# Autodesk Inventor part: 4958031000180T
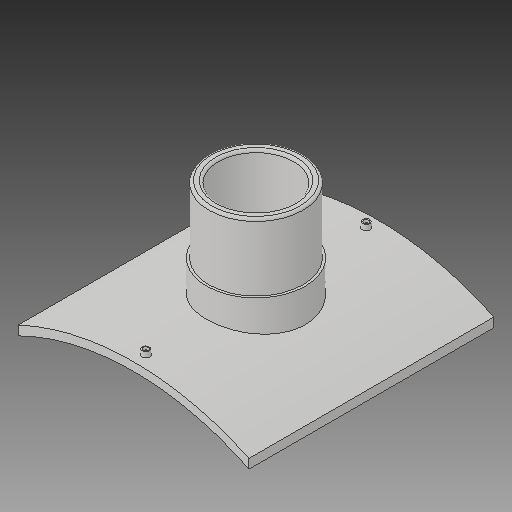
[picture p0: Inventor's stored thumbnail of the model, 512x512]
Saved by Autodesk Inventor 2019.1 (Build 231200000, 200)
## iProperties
Created: 2017-10
Part Number: 4958031000180T
Material: Generic
Description: PLASSON BRANCH SADDLE 1000x180
Document SubType Name: Modeling
Designer: KIM
Mass: 2754.05 g
Surface Area: 3037.44 cm^2
Volume: 2754.05 cm^3
Density: 1 g/cm^3
Appearance: Default
Author: KIM
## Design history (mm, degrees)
derived "495803.ipt"
feature "Solid1::495803.ipt"
tag "TaggingFeature1"
body "Solid1"
other parameters: "d1" = 16, "d2" = 443, "d4" = 0, "d12" = 525.6, "d13" = 14, "d14" = 211.5, "d16" = 5 deg, "d18" = 4, "d19" = 14, "d20" = 0, "d21" = 3, "d22" = 0, "d24" = 189, "d25" = 16, "d26" = 144, "d28" = 0, "d29" = 9.6, "d31" = 0, "d32" = 92, "d33" = 0, "d37" = 128.8, "d38" = 0, "d39" = 5, "B_" = 443, "H_" = 184, "x_" = 16, "D_" = 16
